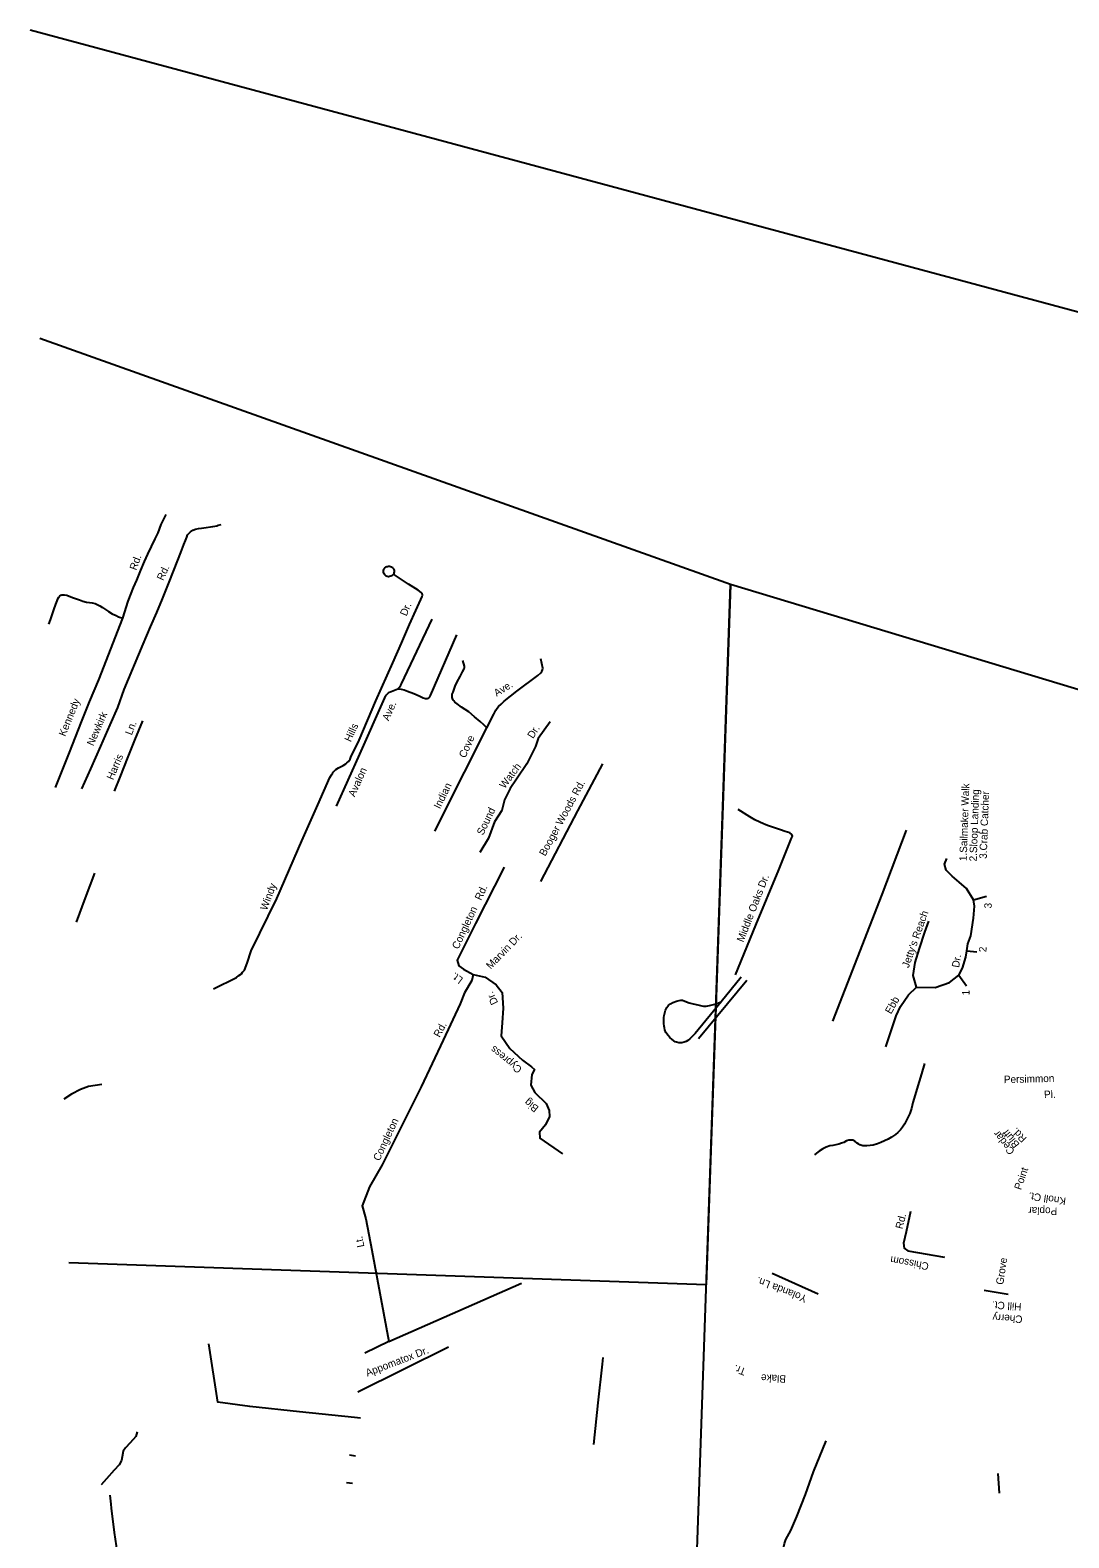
# Model space of a CAD drawing. Extents: x 2308163 to 2335412, y -96774 to 125428.
# Drawn here: x 2322640.83 to 2322658.65, y 104421.73 to 104447.59 of the extents above; entities that cross this region are included whole.
import ezdxf

# ---------------------------------------------------------------- set-up
doc = ezdxf.new("R2010")
doc.units = 0
for name, color, linetype in [('Old_Level_10', 7, 'Continuous'), ('Old_Level_35', 7, 'Continuous'), ('Old_Level_63', 7, 'Continuous')]:
    doc.layers.add(name, color=color, linetype=linetype)

msp = doc.modelspace()

# ---------------------------------------------------------------- linework, layer by layer
at = {"layer": 'Old_Level_35'}
for p, q in [((2322652.292, 104430.296), (2322653.121, 104431.296)), ((2322653.025, 104431.345), (2322652.682, 104430.927)), ((2322646.495, 104423.785), (2322646.39, 104423.795)), ((2322646.408, 104423.131), (2322646.307, 104423.149)), ((2322642.135, 104422.742), (2322642.044, 104422.64)), ((2322657.431, 104422.836), (2322657.451, 104422.499)), ((2322646.358, 104422.663), (2322646.257, 104422.673)), ((2322642.191, 104422.464), (2322642.209, 104422.305))]:
    msp.add_line(p, q, dxfattribs=at)
for points in [[(2322642.417, 104437.507), (2322642.507, 104437.798), (2322642.599, 104438.03), (2322642.654, 104438.157), (2322642.726, 104438.331), (2322642.788, 104438.478), (2322642.843, 104438.605), (2322642.971, 104438.867), (2322643.021, 104438.968), (2322643.076, 104439.115), (2322643.159, 104439.285)], [(2322641.713, 104434.578), (2322641.868, 104434.923), (2322642.038, 104435.31), (2322642.2, 104435.678), (2322642.328, 104435.976), (2322642.439, 104436.281), (2322642.767, 104437.059), (2322642.893, 104437.357), (2322642.998, 104437.604), (2322643.095, 104437.84), (2322643.2, 104438.095), (2322643.296, 104438.343), (2322643.409, 104438.631), (2322643.463, 104438.768), (2322643.491, 104438.837), (2322643.513, 104438.895), (2322643.528, 104438.934), (2322643.553, 104438.965), (2322643.577, 104438.987), (2322643.616, 104439.013), (2322643.664, 104439.032), (2322643.716, 104439.043), (2322643.767, 104439.049), (2322643.844, 104439.059), (2322643.922, 104439.071), (2322643.961, 104439.079), (2322644.027, 104439.091), (2322644.055, 104439.099), (2322644.106, 104439.113)], [(2322645.764, 104434.303), (2322645.971, 104434.774), (2322645.996, 104434.821), (2322646.012, 104434.843), (2322646.028, 104434.867), (2322646.048, 104434.89), (2322646.072, 104434.912), (2322646.116, 104434.939), (2322646.195, 104434.98), (2322646.242, 104435.006), (2322646.262, 104435.022), (2322646.289, 104435.049), (2322646.315, 104435.09), (2322646.326, 104435.119), (2322646.47, 104435.411), (2322646.757, 104436.088), (2322647.05, 104436.739), (2322647.196, 104437.076), (2322647.336, 104437.397), (2322647.442, 104437.636), (2322647.527, 104437.828), (2322647.55, 104437.875), (2322647.556, 104437.9), (2322647.55, 104437.927), (2322647.536, 104437.945), (2322647.482, 104437.984), (2322647.32, 104438.087), (2322647.058, 104438.261)], [(2322647.058, 104438.261), (2322647.045, 104438.244), (2322647.031, 104438.233), (2322647.015, 104438.224), (2322646.994, 104438.218), (2322646.973, 104438.217), (2322646.953, 104438.222), (2322646.937, 104438.229), (2322646.923, 104438.239), (2322646.911, 104438.251), (2322646.901, 104438.266), (2322646.895, 104438.278), (2322646.891, 104438.294), (2322646.89, 104438.309), (2322646.891, 104438.323), (2322646.895, 104438.338), (2322646.901, 104438.351), (2322646.91, 104438.364), (2322646.92, 104438.375), (2322646.932, 104438.384), (2322646.945, 104438.391), (2322646.958, 104438.395), (2322646.976, 104438.399), (2322646.993, 104438.398), (2322647.011, 104438.394), (2322647.024, 104438.388), (2322647.037, 104438.378), (2322647.046, 104438.371), (2322647.055, 104438.36), (2322647.061, 104438.35), (2322647.066, 104438.338), (2322647.07, 104438.325), (2322647.071, 104438.312), (2322647.071, 104438.298), (2322647.069, 104438.286), (2322647.065, 104438.273), (2322647.058, 104438.261)], [(2322641.147, 104437.403), (2322641.173, 104437.48), (2322641.232, 104437.651), (2322641.266, 104437.747), (2322641.289, 104437.805), (2322641.304, 104437.84), (2322641.32, 104437.867), (2322641.335, 104437.887), (2322641.351, 104437.898), (2322641.371, 104437.906), (2322641.384, 104437.908), (2322641.413, 104437.906), (2322641.453, 104437.899), (2322641.555, 104437.86), (2322641.671, 104437.818), (2322641.733, 104437.796), (2322641.795, 104437.779), (2322641.845, 104437.774), (2322641.891, 104437.769), (2322641.943, 104437.755), (2322641.977, 104437.743), (2322642.024, 104437.718), (2322642.07, 104437.687), (2322642.101, 104437.665), (2322642.169, 104437.619), (2322642.231, 104437.583), (2322642.3, 104437.55), (2322642.343, 104437.529), (2322642.417, 104437.507)], [(2322641.26, 104434.604), (2322641.499, 104435.202), (2322641.708, 104435.727), (2322641.843, 104436.071), (2322642.005, 104436.446), (2322642.417, 104437.507)], [(2322647.137, 104436.294), (2322647.162, 104436.321), (2322647.186, 104436.355), (2322647.198, 104436.382), (2322647.723, 104437.487)], [(2322647.137, 104436.294), (2322647.195, 104436.287), (2322647.242, 104436.275), (2322647.301, 104436.255), (2322647.409, 104436.213), (2322647.502, 104436.172), (2322647.572, 104436.138), (2322647.609, 104436.129), (2322647.638, 104436.129), (2322647.656, 104436.135), (2322647.668, 104436.142), (2322647.682, 104436.159), (2322647.694, 104436.182), (2322648.147, 104437.218)], [(2322648.665, 104435.623), (2322648.608, 104435.676), (2322648.547, 104435.736), (2322648.451, 104435.816), (2322648.351, 104435.897), (2322648.228, 104435.982), (2322648.151, 104436.035), (2322648.116, 104436.064), (2322648.098, 104436.087), (2322648.086, 104436.1), (2322648.071, 104436.127), (2322648.068, 104436.146), (2322648.065, 104436.17), (2322648.07, 104436.201), (2322648.082, 104436.236), (2322648.102, 104436.29), (2322648.12, 104436.337), (2322648.156, 104436.413), (2322648.202, 104436.506), (2322648.246, 104436.587), (2322648.271, 104436.637), (2322648.279, 104436.662), (2322648.28, 104436.684), (2322648.248, 104436.781)], [(2322648.665, 104435.623), (2322648.78, 104435.859), (2322648.817, 104435.929), (2322648.839, 104435.962), (2322648.865, 104435.992), (2322648.906, 104436.032), (2322648.957, 104436.082), (2322649.176, 104436.252), (2322649.535, 104436.525), (2322649.587, 104436.57), (2322649.604, 104436.592), (2322649.619, 104436.617), (2322649.625, 104436.648), (2322649.59, 104436.809)], [(2322646.08, 104434.279), (2322646.481, 104435.172), (2322646.911, 104436.139), (2322646.924, 104436.169), (2322646.933, 104436.182), (2322646.942, 104436.192), (2322646.953, 104436.205), (2322646.967, 104436.22), (2322646.975, 104436.226), (2322646.993, 104436.236), (2322647.137, 104436.294)], [(2322642.276, 104434.538), (2322642.369, 104434.777), (2322642.507, 104435.126), (2322642.623, 104435.411), (2322642.758, 104435.744)], [(2322649.747, 104435.727), (2322649.541, 104435.44), (2322649.497, 104435.304), (2322649.349, 104435.005), (2322649.174, 104434.746), (2322649.06, 104434.584), (2322648.965, 104434.391), (2322648.92, 104434.206), (2322648.795, 104434.014), (2322648.688, 104433.734), (2322648.541, 104433.484)], [(2322647.77, 104433.852), (2322648.279, 104434.863), (2322648.665, 104435.623)], [(2322649.59, 104432.991), (2322650.221, 104434.203), (2322650.655, 104435.005)], [(2322644.621, 104431.8), (2322645.057, 104432.698), (2322645.487, 104433.688), (2322645.764, 104434.303)], [(2322652.928, 104431.39), (2322653.277, 104432.238), (2322653.671, 104433.19), (2322653.892, 104433.735), (2322653.908, 104433.766), (2322653.897, 104433.793), (2322653.863, 104433.821), (2322653.823, 104433.834), (2322653.781, 104433.847), (2322653.703, 104433.876), (2322653.479, 104433.952), (2322653.436, 104433.965), (2322653.409, 104433.977), (2322653.347, 104434.006), (2322653.262, 104434.048), (2322653.177, 104434.096), (2322652.977, 104434.222)], [(2322654.597, 104430.592), (2322655.444, 104432.767), (2322655.861, 104433.867)], [(2322655.509, 104430.154), (2322655.683, 104430.682), (2322655.761, 104430.846), (2322655.899, 104431.044), (2322656.034, 104431.177), (2322656.353, 104431.173), (2322656.603, 104431.259), (2322656.759, 104431.384), (2322656.822, 104431.505), (2322656.879, 104431.692), (2322656.897, 104431.8), (2322656.916, 104431.922), (2322656.964, 104432.059), (2322657.011, 104432.362), (2322657.032, 104432.564), (2322657.014, 104432.673), (2322656.89, 104432.866), (2322656.764, 104432.979), (2322656.644, 104433.078), (2322656.546, 104433.182), (2322656.513, 104433.285), (2322656.553, 104433.385)], [(2322641.928, 104433.131), (2322641.772, 104432.711), (2322641.614, 104432.293)], [(2322648.961, 104433.235), (2322648.465, 104432.268), (2322648.216, 104431.766), (2322648.154, 104431.642), (2322648.179, 104431.545), (2322648.264, 104431.484), (2322648.425, 104431.392), (2322648.636, 104431.346), (2322648.824, 104431.214), (2322648.926, 104431.085), (2322648.945, 104430.815), (2322648.927, 104430.564), (2322648.91, 104430.343), (2322649.057, 104430.126), (2322649.272, 104429.926), (2322649.429, 104429.807)], [(2322657.014, 104432.673), (2322657.236, 104432.738)], [(2322656.034, 104431.177), (2322655.975, 104431.375), (2322656.012, 104431.598), (2322656.086, 104431.842), (2322656.175, 104432.122), (2322656.247, 104432.308)], [(2322643.973, 104431.145), (2322644.367, 104431.341), (2322644.409, 104431.374), (2322644.45, 104431.403), (2322644.472, 104431.433), (2322644.504, 104431.466), (2322644.549, 104431.59), (2322644.621, 104431.8)], [(2322656.897, 104431.8), (2322657.072, 104431.783)], [(2322648.425, 104431.392), (2322648.404, 104431.291), (2322648.281, 104431.08), (2322648.206, 104430.89), (2322647.915, 104430.269), (2322647.533, 104429.467), (2322646.864, 104428.129), (2322646.651, 104427.752), (2322646.524, 104427.426), (2322646.586, 104427.201), (2322646.69, 104426.667)], [(2322656.759, 104431.384), (2322656.895, 104431.197)], [(2322652.682, 104430.927), (2322652.239, 104430.383), (2322652.187, 104430.33), (2322652.147, 104430.292), (2322652.111, 104430.261), (2322652.085, 104430.243), (2322652.048, 104430.232), (2322652.008, 104430.223), (2322651.954, 104430.222), (2322651.919, 104430.23), (2322651.895, 104430.239), (2322651.841, 104430.277), (2322651.804, 104430.311), (2322651.773, 104430.346), (2322651.733, 104430.401), (2322651.717, 104430.447), (2322651.71, 104430.478), (2322651.707, 104430.505), (2322651.7, 104430.552), (2322651.698, 104430.602), (2322651.702, 104430.654), (2322651.707, 104430.693), (2322651.715, 104430.737), (2322651.729, 104430.78), (2322651.752, 104430.826), (2322651.766, 104430.852), (2322651.782, 104430.867), (2322651.814, 104430.89), (2322651.854, 104430.912), (2322651.917, 104430.934), (2322651.96, 104430.949), (2322651.991, 104430.955), (2322652.019, 104430.951), (2322652.061, 104430.938), (2322652.132, 104430.91), (2322652.202, 104430.888), (2322652.282, 104430.871), (2322652.35, 104430.856), (2322652.38, 104430.853), (2322652.423, 104430.852), (2322652.485, 104430.862), (2322652.576, 104430.887), (2322652.682, 104430.927)], [(2322649.429, 104429.807), (2322649.479, 104429.764), (2322649.437, 104429.679), (2322649.416, 104429.494), (2322649.484, 104429.369), (2322649.681, 104429.179), (2322649.734, 104429.061), (2322649.74, 104428.955), (2322649.668, 104428.812), (2322649.567, 104428.691), (2322649.573, 104428.584), (2322649.96, 104428.32)], [(2322656.174, 104429.866), (2322656.119, 104429.688), (2322656.08, 104429.559), (2322655.97, 104429.199), (2322655.948, 104429.094), (2322655.919, 104429.012), (2322655.894, 104428.951), (2322655.863, 104428.892), (2322655.828, 104428.827), (2322655.796, 104428.777), (2322655.76, 104428.731), (2322655.714, 104428.686), (2322655.672, 104428.647), (2322655.608, 104428.606), (2322655.547, 104428.571), (2322655.487, 104428.54), (2322655.424, 104428.511), (2322655.363, 104428.487), (2322655.292, 104428.467), (2322655.242, 104428.46), (2322655.183, 104428.456), (2322655.153, 104428.455), (2322655.116, 104428.457), (2322655.081, 104428.466), (2322655.064, 104428.474)], [(2322642.057, 104429.509), (2322641.829, 104429.47), (2322641.69, 104429.422), (2322641.536, 104429.343), (2322641.404, 104429.253)], [(2322655.064, 104428.474), (2322655.047, 104428.481), (2322655.015, 104428.503), (2322654.979, 104428.533), (2322654.963, 104428.542), (2322654.943, 104428.549), (2322654.911, 104428.552), (2322654.872, 104428.55), (2322654.836, 104428.538), (2322654.785, 104428.512), (2322654.746, 104428.498), (2322654.703, 104428.485), (2322654.648, 104428.472), (2322654.6, 104428.462), (2322654.549, 104428.452), (2322654.483, 104428.431), (2322654.427, 104428.404), (2322654.367, 104428.362), (2322654.319, 104428.328), (2322654.287, 104428.301)], [(2322655.93, 104427.33), (2322655.857, 104426.981), (2322655.812, 104426.785), (2322655.824, 104426.7), (2322655.884, 104426.652), (2322656.514, 104426.547)], [(2322646.69, 104426.667), (2322646.982, 104425.099), (2322646.568, 104424.897)], [(2322646.982, 104425.099), (2322649.256, 104426.097)], [(2322653.556, 104426.269), (2322654.35, 104425.917)], [(2322657.61, 104425.903), (2322657.195, 104425.971)], [(2322646.39, 104423.795), (2322645.45, 104423.892), (2322644.596, 104423.983), (2322644.047, 104424.055), (2322643.895, 104425.059)], [(2322646.451, 104424.236), (2322648.004, 104425.006)], [(2322650.655, 104424.826), (2322650.642, 104424.711), (2322650.565, 104424.046), (2322650.493, 104423.332)], [(2322642.663, 104423.549), (2322642.64, 104423.466), (2322642.543, 104423.36), (2322642.461, 104423.274), (2322642.422, 104423.216), (2322642.408, 104423.122), (2322642.393, 104423.059), (2322642.354, 104422.985), (2322642.268, 104422.891), (2322642.135, 104422.742)], [(2322653.754, 104421.556), (2322653.768, 104421.634), (2322653.794, 104421.704), (2322653.876, 104421.855), (2322653.979, 104422.094), (2322654.128, 104422.473), (2322654.265, 104422.864), (2322654.484, 104423.394)], [(2322642.209, 104422.305), (2322642.217, 104422.242), (2322642.269, 104421.821), (2322642.334, 104421.364), (2322642.371, 104421.06), (2322642.368, 104420.958), (2322642.329, 104420.86), (2322642.236, 104420.731), (2322642.139, 104420.633)]]:
    msp.add_lwpolyline(points, dxfattribs=at)
at = {"layer": 'Old_Level_63'}
for p, q in [((2322652.841, 104438.082), (2322640.993, 104442.303)), ((2322668.719, 104433.293), (2322652.841, 104438.082))]:
    msp.add_line(p, q, dxfattribs=at)
for points in [[(2322693.641, 104432.632), (2322688.481, 104434.771), (2322640.826, 104447.593)], [(2322652.841, 104438.079), (2322652.427, 104426.073), (2322641.492, 104426.45)], [(2322668.719, 104433.293), (2322667.834, 104407.621), (2322651.808, 104408.127), (2322652.841, 104438.082)]]:
    msp.add_lwpolyline(points, dxfattribs=at)

# ---------------------------------------------------------------- texts
at = {"layer": 'Old_Level_10'}
for s, height, rotation, p in [('Rd.', 0.1282, 69.6167, (2322642.646, 104438.318)), ('Rd.', 0.1282, 65.0847, (2322643.108, 104438.141)), ('Dr.', 0.1282, 67.3169, (2322647.284, 104437.532)), ('Ave.', 0.1282, 32.0499, (2322648.831, 104436.155)), ('Kennedy', 0.1282, 67.8467, (2322641.428, 104435.468)), ('Ave.', 0.1282, 66.0506, (2322646.976, 104435.734)), ('Newkirk', 0.1282, 66.499, (2322641.91, 104435.305)), ('Ln.', 0.1282, 69.1108, (2322642.57, 104435.49)), ('Hills', 0.1282, 65.6411, (2322646.327, 104435.373)), ('Cove', 0.1282, 65.514, (2322648.292, 104435.097)), ('Dr.', 0.1282, 57.3171, (2322649.455, 104435.43)), ('Harris', 0.1282, 67.3307, (2322642.251, 104434.721)), ('Avalon', 0.1282, 65.8193, (2322646.393, 104434.43)), ('Watch', 0.1282, 53.1139, (2322648.968, 104434.572)), ('Indian ', 0.1282, 63.7995, (2322647.858, 104434.224)), ('Booger Woods Rd.', 0.12816, 61.6242, (2322649.665, 104433.413)), ('1.Sailmaker Walk', 0.12816, 88.0247, (2322656.896, 104433.336)), ('2.Sloop Landing', 0.12816, 88.0247, (2322657.068, 104433.331)), ('3.Crab Catcher', 0.12816, 88.0247, (2322657.24, 104433.376)), ('Sound ', 0.1282, 64.3347, (2322648.598, 104433.772)), ('Middle Oaks Dr.', 0.12816, 68.7633, (2322653.064, 104431.938)), ('Windy', 0.1282, 69.4786, (2322644.888, 104432.484)), ('Congleton   Rd.', 0.12816, 64.9615, (2322648.173, 104431.817)), ('3', 0.128, 88.0247, (2322657.324, 104432.525)), ("Jetty's Reach", 0.12816, 70.5106, (2322655.9, 104431.497)), ('Marvin Dr.', 0.1282, 45.8234, (2322648.728, 104431.475)), ('2', 0.128, 88.0247, (2322657.234, 104431.774)), ('Dr.', 0.1282, 80.239, (2322656.764, 104431.504)), ('Lt.', 0.1282, 143.6523, (2322648.266, 104431.326)), ('Dr.', 0.1282, 115.5158, (2322648.859, 104430.91)), ('1', 0.128, 88.0247, (2322656.943, 104431.032)), ('Ebb ', 0.1282, 60.3233, (2322655.597, 104430.705)), ('Rd.', 0.1282, 61.5377, (2322647.852, 104430.304)), ('Cypress', 0.1282, 140.9663, (2322649.277, 104429.786)), ('Persimmon ', 0.1282, 1.5076, (2322657.535, 104429.529)), ('Big', 0.1282, 141.4721, (2322649.563, 104429.119)), ('Pl.', 0.1282, 1.5076, (2322658.224, 104429.272)), ('Congleton', 0.1282, 64.9413, (2322646.82, 104428.185)), ('Cedar ', 0.1282, 128.3484, (2322657.729, 104428.364)), ('Bluff', 0.1282, 128.3484, (2322657.811, 104428.48)), ('Rd.', 0.1282, 134.7737, (2322657.935, 104428.589)), ('Point', 0.1282, 71.0018, (2322657.827, 104427.689)), ('Knoll Ct.', 0.1282, 171.486, (2322658.606, 104427.562)), ('Poplar', 0.1282, 178.5533, (2322658.451, 104427.394)), ('Rd.', 0.1282, 75.3776, (2322655.793, 104427.018)), ('Lt. ', 0.1282, 101.4483, (2322646.563, 104426.726)), ('Chissom', 0.1282, 169.6256, (2322656.254, 104426.445)), ('Grove ', 0.1282, 81.4647, (2322657.522, 104426.065)), ('Yolanda Ln.', 0.12816, 158.6402, (2322654.168, 104425.878)), ('Cherry ', 0.1282, 176.1975, (2322657.857, 104425.54)), ('Hill Ct.', 0.1282, 176.1975, (2322657.839, 104425.756)), ('Appomatox Dr.', 0.12816, 20.8983, (2322646.611, 104424.495)), ('Tr.', 0.1282, 159.6034, (2322653.121, 104424.63)), ('Blake', 0.1282, 177.5682, (2322653.797, 104424.518))]:
    msp.add_text(s, height=height, rotation=rotation, dxfattribs=at).set_placement(p)

doc.saveas('drawing.dxf')
